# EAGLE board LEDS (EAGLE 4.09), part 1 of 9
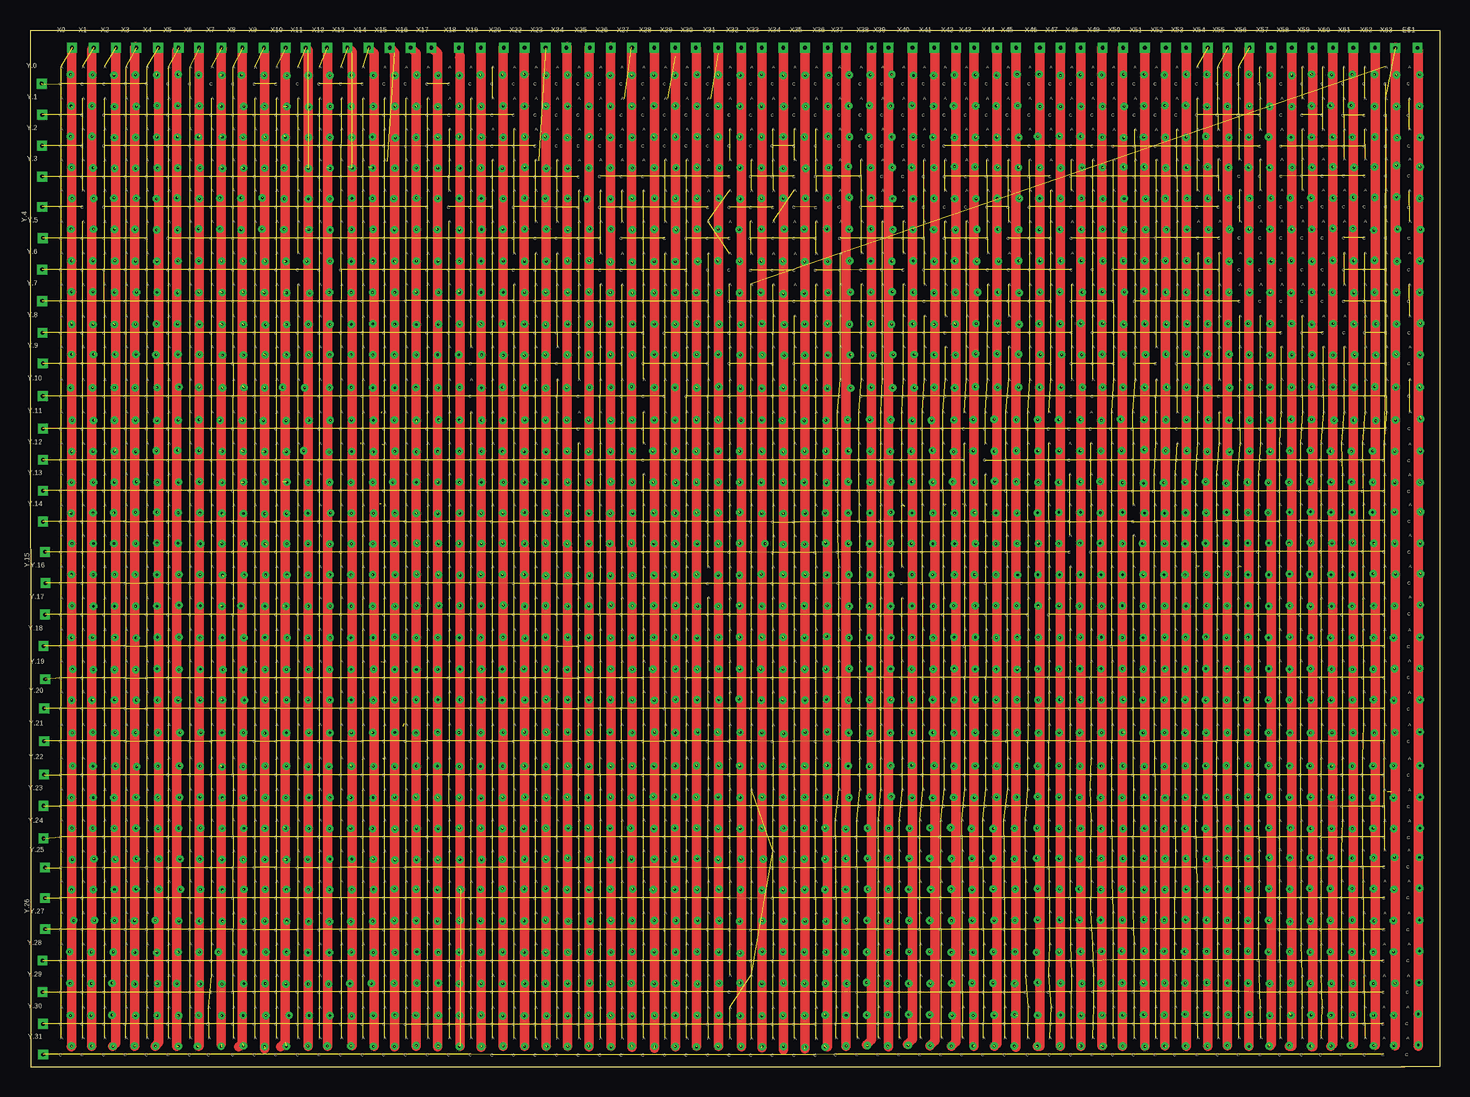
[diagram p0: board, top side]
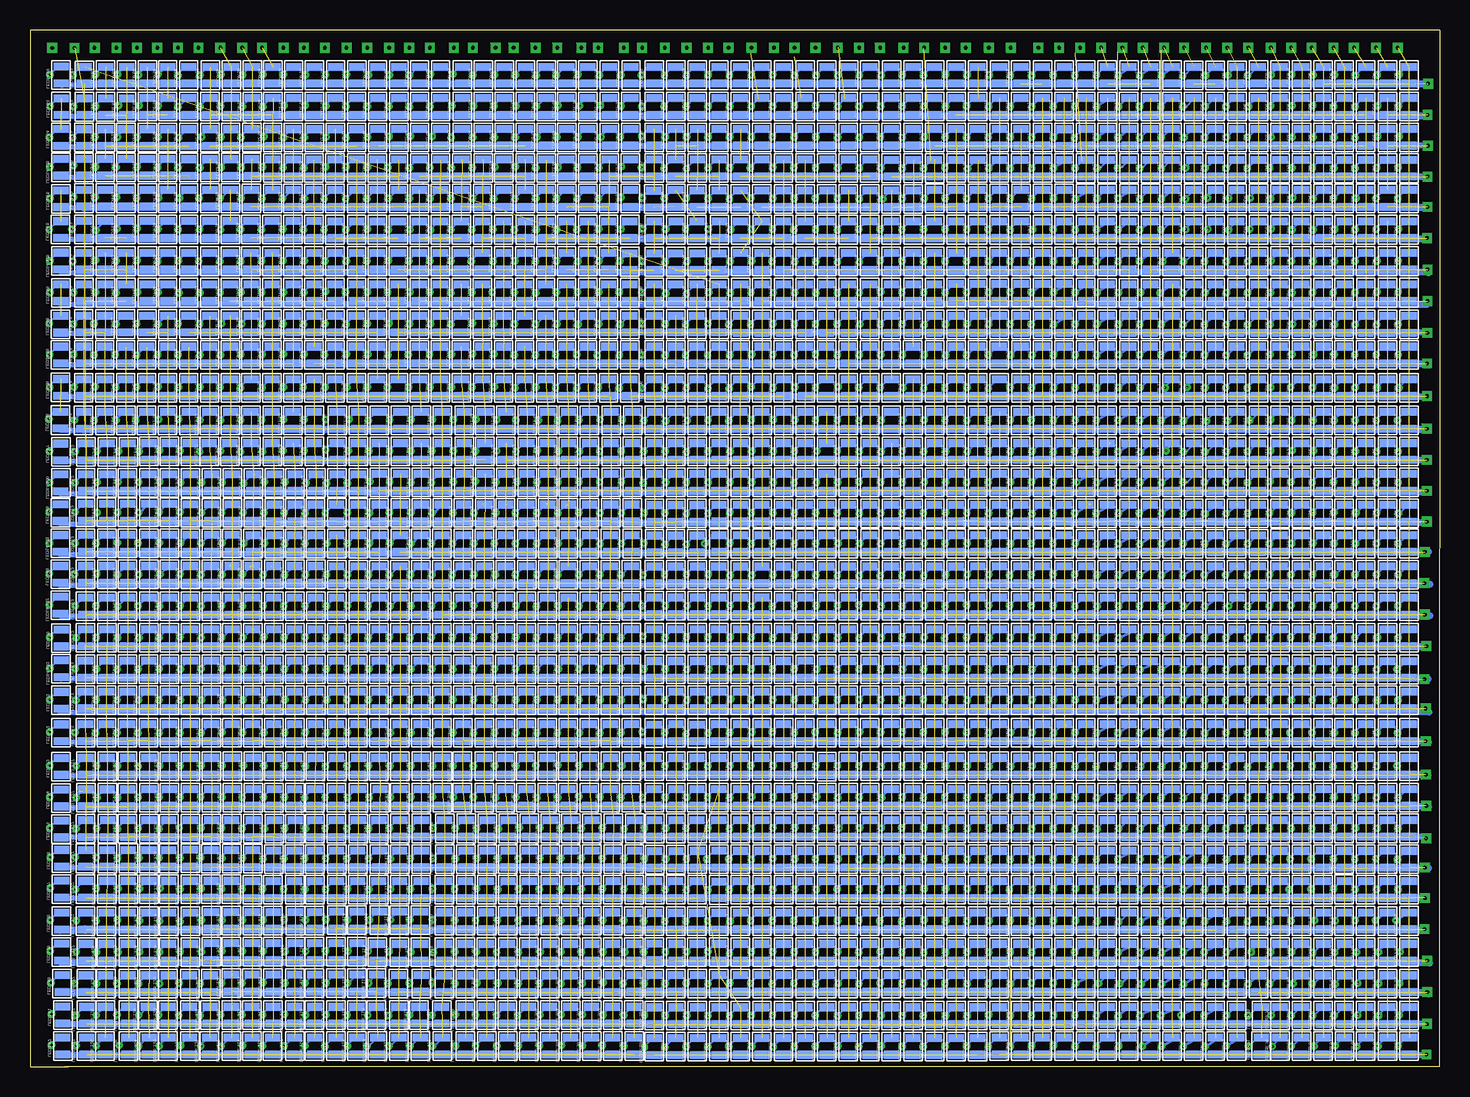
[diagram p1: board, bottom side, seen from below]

Size 117.52 x 86.45 mm. Coordinates in mm from the lower left corner, seen from the top.
Outline: 114.61,0 0.05,0 0,86.45 114.96,86.45
Outline: 114.96,86.45 114.99,86.45
Outline: 114.96,86.45 117.52,86.45 117.52,0 114.29,0
Copper layers used: Top, Bottom

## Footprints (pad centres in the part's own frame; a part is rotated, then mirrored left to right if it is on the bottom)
PAD0.012 = drill 0.305 pad 0.305 square: P$ 0,0
LED_603 = smd 1.27 x 0.635 bottom: P$A 0.004,-0.7; P$K 0.004,0.7

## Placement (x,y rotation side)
E$1  [PAD0.012]  115.68,84.96 0 top
LED0.0  LED_CROSS1/2  [LED_603]  2.57,82.68 180 top
LED0.1  LED_CROSS1/2  [LED_603]  4.37,82.68 180 top
LED0.2  LED_CROSS1/2  [LED_603]  6.18,82.68 180 top
LED0.3  LED_CROSS1/2  [LED_603]  7.97,82.68 180 top
LED0.4  LED_CROSS1/2  [LED_603]  9.72,82.68 180 top
LED0.5  LED_CROSS1/2  [LED_603]  11.52,82.68 180 top
LED0.6  LED_CROSS1/2  [LED_603]  13.32,82.68 180 top
LED0.7  LED_CROSS1/2  [LED_603]  15.12,82.68 180 top
LED0.8  LED_CROSS1/2  [LED_603]  16.92,82.67 180 top
LED0.9  LED_CROSS1/2  [LED_603]  18.72,82.67 180 top
LED0.10  LED_CROSS1/2  [LED_603]  20.52,82.67 180 top
LED0.11  LED_CROSS1/2  [LED_603]  22.32,82.68 180 top
LED0.12  LED_CROSS1/2  [LED_603]  24.12,82.68 180 top
LED0.13  LED_CROSS1/2  [LED_603]  25.91,82.68 180 top
LED0.14  LED_CROSS1/2  [LED_603]  27.72,82.68 180 top
LED0.15  LED_CROSS1/2  [LED_603]  29.52,82.68 180 top
LED0.16  LED_CROSS1/2  [LED_603]  31.3,82.68 180 top
LED0.17  LED_CROSS1/2  [LED_603]  33.12,82.68 180 top
LED0.18  LED_CROSS1/2  [LED_603]  34.92,82.68 180 top
LED0.19  LED_CROSS1/2  [LED_603]  36.7,82.68 180 top
LED0.20  LED_CROSS1/2  [LED_603]  38.52,82.68 180 top
LED0.21  LED_CROSS1/2  [LED_603]  40.32,82.68 180 top
LED0.22  LED_CROSS1/2  [LED_603]  42.12,82.68 180 top
LED0.23  LED_CROSS1/2  [LED_603]  43.9,82.68 180 top
LED0.24  LED_CROSS1/2  [LED_603]  45.7,82.68 180 top
LED0.25  LED_CROSS1/2  [LED_603]  47.51,82.68 180 top
LED0.26  LED_CROSS1/2  [LED_603]  49.28,82.68 180 top
LED0.27  LED_CROSS1/2  [LED_603]  51.1,82.68 180 top
LED0.28  LED_CROSS1/2  [LED_603]  52.91,82.68 180 top
LED0.29  LED_CROSS1/2  [LED_603]  54.71,82.68 180 top
LED0.30  LED_CROSS1/2  [LED_603]  56.51,82.68 180 top
LED0.31  LED_CROSS1/2  [LED_603]  58.3,82.68 180 top
LED0.32  LED_CROSS1/2  [LED_603]  60.09,82.68 180 top
LED0.33  LED_CROSS1/2  [LED_603]  61.91,82.68 180 top
LED0.34  LED_CROSS1/2  [LED_603]  63.7,82.68 180 top
LED0.35  LED_CROSS1/2  [LED_603]  65.49,82.68 180 top
LED0.37  LED_CROSS1/2  [LED_603]  67.42,82.68 180 top
LED0.38  LED_CROSS1/2  [LED_603]  69.22,82.68 180 top
LED0.39  LED_CROSS1/2  [LED_603]  71.02,82.68 180 top
LED0.40  LED_CROSS1/2  [LED_603]  72.77,82.68 180 top
LED0.41  LED_CROSS1/2  [LED_603]  74.5,82.68 180 top
LED0.42  LED_CROSS1/2  [LED_603]  76.22,82.68 180 top
LED0.43  LED_CROSS1/2  [LED_603]  78,82.68 180 top
LED0.44  LED_CROSS1/2  [LED_603]  79.75,82.68 180 top
LED0.45  LED_CROSS1/2  [LED_603]  81.47,82.68 180 top
LED0.46  LED_CROSS1/2  [LED_603]  83.3,82.68 180 top
LED0.47  LED_CROSS1/2  [LED_603]  85.05,82.68 180 top
LED0.48  LED_CROSS1/2  [LED_603]  86.77,82.68 180 top
LED0.49  LED_CROSS1/2  [LED_603]  88.55,82.68 180 top
LED0.50  LED_CROSS1/2  [LED_603]  90.27,82.68 180 top
LED0.51  LED_CROSS1/2  [LED_603]  92.05,82.68 180 top
LED0.52  LED_CROSS1/2  [LED_603]  93.82,82.68 180 top
LED0.53  LED_CROSS1/2  [LED_603]  95.55,82.68 180 top
LED0.54  LED_CROSS1/2  [LED_603]  97.27,82.68 180 top
LED0.55  LED_CROSS1/2  [LED_603]  99,82.68 180 top
LED0.56  LED_CROSS1/2  [LED_603]  100.75,82.68 180 top
LED0.57  LED_CROSS1/2  [LED_603]  102.5,82.68 180 top
LED0.58  LED_CROSS1/2  [LED_603]  104.3,82.68 180 top
LED0.59  LED_CROSS1/2  [LED_603]  106.05,82.68 180 top
LED0.60  LED_CROSS1/2  [LED_603]  107.75,82.68 180 top
LED0.61  LED_CROSS1/2  [LED_603]  109.47,82.68 180 top
LED0.62  LED_CROSS1/2  [LED_603]  111.22,82.68 180 top
LED1.0  LED_CROSS1/2  [LED_603]  2.57,80.08 180 top
LED1.1  LED_CROSS1/2  [LED_603]  4.37,80.08 180 top
LED1.2  LED_CROSS1/2  [LED_603]  6.18,80.08 180 top
LED1.3  LED_CROSS1/2  [LED_603]  7.97,80.08 180 top
LED1.4  LED_CROSS1/2  [LED_603]  9.72,80.08 180 top
LED1.5  LED_CROSS1/2  [LED_603]  11.52,80.08 180 top
LED1.6  LED_CROSS1/2  [LED_603]  13.32,80.08 180 top
LED1.7  LED_CROSS1/2  [LED_603]  15.12,80.08 180 top
LED1.8  LED_CROSS1/2  [LED_603]  16.92,80.08 180 top
LED1.9  LED_CROSS1/2  [LED_603]  18.72,80.08 180 top
LED1.10  LED_CROSS1/2  [LED_603]  20.52,80.08 180 top
LED1.11  LED_CROSS1/2  [LED_603]  22.32,80.08 180 top
LED1.12  LED_CROSS1/2  [LED_603]  24.12,80.08 180 top
LED1.13  LED_CROSS1/2  [LED_603]  25.92,80.08 180 top
LED1.14  LED_CROSS1/2  [LED_603]  27.72,80.08 180 top
LED1.15  LED_CROSS1/2  [LED_603]  29.52,80.08 180 top
LED1.16  LED_CROSS1/2  [LED_603]  31.33,80.08 180 top
LED1.17  LED_CROSS1/2  [LED_603]  33.12,80.08 180 top
LED1.18  LED_CROSS1/2  [LED_603]  34.92,80.08 180 top
LED1.19  LED_CROSS1/2  [LED_603]  36.72,80.08 180 top
LED1.20  LED_CROSS1/2  [LED_603]  38.52,80.08 180 top
LED1.21  LED_CROSS1/2  [LED_603]  40.32,80.08 180 top
LED1.22  LED_CROSS1/2  [LED_603]  42.12,80.08 180 top
LED1.23  LED_CROSS1/2  [LED_603]  43.9,80.08 180 top
LED1.24  LED_CROSS1/2  [LED_603]  45.7,80.08 180 top
LED1.25  LED_CROSS1/2  [LED_603]  47.51,80.08 180 top
LED1.26  LED_CROSS1/2  [LED_603]  49.31,80.08 180 top
LED1.27  LED_CROSS1/2  [LED_603]  51.1,80.08 180 top
LED1.28  LED_CROSS1/2  [LED_603]  52.91,80.08 180 top
LED1.29  LED_CROSS1/2  [LED_603]  54.71,80.08 180 top
LED1.30  LED_CROSS1/2  [LED_603]  56.51,80.08 180 top
LED1.31  LED_CROSS1/2  [LED_603]  58.3,80.08 180 top
LED1.32  LED_CROSS1/2  [LED_603]  60.09,80.08 180 top
LED1.33  LED_CROSS1/2  [LED_603]  61.91,80.08 180 top
LED1.34  LED_CROSS1/2  [LED_603]  63.7,80.08 180 top
LED1.35  LED_CROSS1/2  [LED_603]  65.49,80.08 180 top
LED1.36  LED_CROSS1/2  [LED_603]  114.97,56.65 180 top
LED1.37  LED_CROSS1/2  [LED_603]  67.44,80.08 180 top
LED1.38  LED_CROSS1/2  [LED_603]  69.22,80.08 180 top
LED1.39  LED_CROSS1/2  [LED_603]  71.02,80.08 180 top
LED1.40  LED_CROSS1/2  [LED_603]  72.77,80.08 180 top
LED1.41  LED_CROSS1/2  [LED_603]  74.5,80.08 180 top
LED1.42  LED_CROSS1/2  [LED_603]  76.22,80.08 180 top
LED1.43  LED_CROSS1/2  [LED_603]  78,80.08 180 top
LED1.44  LED_CROSS1/2  [LED_603]  79.75,80.08 180 top
LED1.45  LED_CROSS1/2  [LED_603]  81.47,80.08 180 top
LED1.46  LED_CROSS1/2  [LED_603]  83.3,80.08 180 top
LED1.47  LED_CROSS1/2  [LED_603]  85.05,80.08 180 top
LED1.48  LED_CROSS1/2  [LED_603]  86.77,80.08 180 top
LED1.49  LED_CROSS1/2  [LED_603]  88.55,80.08 180 top
LED1.50  LED_CROSS1/2  [LED_603]  90.3,80.08 180 top
LED1.51  LED_CROSS1/2  [LED_603]  92.07,80.08 180 top
LED1.52  LED_CROSS1/2  [LED_603]  93.82,80.08 180 top
LED1.53  LED_CROSS1/2  [LED_603]  95.55,80.08 180 top
LED1.54  LED_CROSS1/2  [LED_603]  97.27,80.08 180 top
LED1.55  LED_CROSS1/2  [LED_603]  99,80.08 180 top
LED1.56  LED_CROSS1/2  [LED_603]  100.75,80.08 180 top
LED1.57  LED_CROSS1/2  [LED_603]  102.52,80.08 180 top
LED1.58  LED_CROSS1/2  [LED_603]  104.3,80.08 180 top
LED1.59  LED_CROSS1/2  [LED_603]  106.05,80.08 180 top
LED1.60  LED_CROSS1/2  [LED_603]  107.75,80.08 180 top
LED1.61  LED_CROSS1/2  [LED_603]  109.47,80.06 180 top
LED1.62  LED_CROSS1/2  [LED_603]  111.22,80.06 180 top
LED1.63  LED_CROSS1/2  [LED_603]  113,80.06 180 top
LED1.64  LED_CROSS1/2  [LED_603]  114.92,80.06 180 top
LED1.65  LED_CROSS1/2  [LED_603]  114.94,72.39 180 top
LED1.66  LED_CROSS1/2  [LED_603]  114.94,64.55 180 top
LED2.0  LED_CROSS1/2  [LED_603]  2.57,77.51 180 top
LED2.1  LED_CROSS1/2  [LED_603]  4.37,77.51 180 top
LED2.2  LED_CROSS1/2  [LED_603]  6.18,77.51 180 top
LED2.3  LED_CROSS1/2  [LED_603]  7.97,77.51 180 top
LED2.4  LED_CROSS1/2  [LED_603]  9.72,77.51 180 top
LED2.5  LED_CROSS1/2  [LED_603]  11.52,77.51 180 top
LED2.6  LED_CROSS1/2  [LED_603]  13.33,77.51 180 top
LED2.7  LED_CROSS1/2  [LED_603]  15.12,77.51 180 top
LED2.8  LED_CROSS1/2  [LED_603]  16.92,77.51 180 top
LED2.9  LED_CROSS1/2  [LED_603]  18.73,77.5 180 top
LED2.10  LED_CROSS1/2  [LED_603]  20.52,77.5 180 top
LED2.11  LED_CROSS1/2  [LED_603]  22.32,77.5 180 top
LED2.12  LED_CROSS1/2  [LED_603]  24.12,77.51 180 top
LED2.13  LED_CROSS1/2  [LED_603]  25.92,77.51 180 top
LED2.14  LED_CROSS1/2  [LED_603]  27.72,77.5 180 top
LED2.15  LED_CROSS1/2  [LED_603]  29.51,77.51 180 top
LED2.16  LED_CROSS1/2  [LED_603]  31.33,77.48 180 top
LED2.17  LED_CROSS1/2  [LED_603]  33.12,77.51 180 top
LED2.18  LED_CROSS1/2  [LED_603]  34.92,77.51 180 top
LED2.19  LED_CROSS1/2  [LED_603]  36.73,77.51 180 top
LED2.20  LED_CROSS1/2  [LED_603]  38.52,77.51 180 top
LED2.21  LED_CROSS1/2  [LED_603]  40.32,77.51 180 top
LED2.22  LED_CROSS1/2  [LED_603]  42.12,77.51 180 top
LED2.23  LED_CROSS1/2  [LED_603]  43.9,77.51 180 top
LED2.24  LED_CROSS1/2  [LED_603]  45.73,77.51 180 top
LED2.25  LED_CROSS1/2  [LED_603]  47.51,77.51 180 top
LED2.26  LED_CROSS1/2  [LED_603]  49.31,77.51 180 top
LED2.27  LED_CROSS1/2  [LED_603]  51.1,77.51 180 top
LED2.28  LED_CROSS1/2  [LED_603]  52.92,77.51 180 top
LED2.29  LED_CROSS1/2  [LED_603]  54.71,77.51 180 top
LED2.30  LED_CROSS1/2  [LED_603]  56.51,77.51 180 top
LED2.31  LED_CROSS1/2  [LED_603]  58.3,77.51 180 top
LED2.32  LED_CROSS1/2  [LED_603]  60.09,77.51 180 top
LED2.33  LED_CROSS1/2  [LED_603]  61.89,77.51 180 top
LED2.34  LED_CROSS1/2  [LED_603]  63.7,77.51 180 top
LED2.35  LED_CROSS1/2  [LED_603]  65.5,77.51 180 top
LED2.36  LED_CROSS1/2  [LED_603]  114.99,53.93 180 top
LED2.37  LED_CROSS1/2  [LED_603]  67.44,77.51 180 top
LED2.38  LED_CROSS1/2  [LED_603]  69.22,77.51 180 top
LED2.39  LED_CROSS1/2  [LED_603]  71.02,77.51 180 top
LED2.40  LED_CROSS1/2  [LED_603]  72.77,77.51 180 top
LED2.41  LED_CROSS1/2  [LED_603]  74.5,77.51 180 top
LED2.42  LED_CROSS1/2  [LED_603]  76.22,77.51 180 top
LED2.43  LED_CROSS1/2  [LED_603]  78,77.51 180 top
LED2.44  LED_CROSS1/2  [LED_603]  79.75,77.51 180 top
LED2.45  LED_CROSS1/2  [LED_603]  81.5,77.51 180 top
LED2.46  LED_CROSS1/2  [LED_603]  83.3,77.51 180 top
LED2.47  LED_CROSS1/2  [LED_603]  85.05,77.51 180 top
LED2.48  LED_CROSS1/2  [LED_603]  86.77,77.51 180 top
LED2.49  LED_CROSS1/2  [LED_603]  88.55,77.51 180 top
LED2.50  LED_CROSS1/2  [LED_603]  90.3,77.48 180 top
LED2.51  LED_CROSS1/2  [LED_603]  92.07,77.48 180 top
LED2.52  LED_CROSS1/2  [LED_603]  93.82,77.48 180 top
LED2.53  LED_CROSS1/2  [LED_603]  95.57,77.48 180 top
LED2.54  LED_CROSS1/2  [LED_603]  97.3,77.48 180 top
LED2.55  LED_CROSS1/2  [LED_603]  99.02,77.48 180 top
LED2.56  LED_CROSS1/2  [LED_603]  100.8,77.48 180 top
LED2.57  LED_CROSS1/2  [LED_603]  102.52,77.48 180 top
LED2.58  LED_CROSS1/2  [LED_603]  104.3,77.48 180 top
LED2.59  LED_CROSS1/2  [LED_603]  106.05,77.48 180 top
LED2.60  LED_CROSS1/2  [LED_603]  107.75,77.48 180 top
LED2.61  LED_CROSS1/2  [LED_603]  109.52,77.48 180 top
LED2.62  LED_CROSS1/2  [LED_603]  111.25,77.48 180 top
LED2.63  LED_CROSS1/2  [LED_603]  113.02,77.48 180 top
LED2.64  LED_CROSS1/2  [LED_603]  114.95,77.5 180 top
LED2.65  LED_CROSS1/2  [LED_603]  114.97,69.81 180 top
LED2.66  LED_CROSS1/2  [LED_603]  114.97,61.92 180 top
LED2.67  LED_CROSS1/2  [LED_603]  114.96,51.27 180 top
LED2.68  LED_CROSS1/2  [LED_603]  114.98,46.21 180 top
LED2.69  LED_CROSS1/2  [LED_603]  114.98,41.06 180 top
LED2.70  LED_CROSS1/2  [LED_603]  114.93,35.76 180 top
LED2.71  LED_CROSS1/2  [LED_603]  114.93,30.56 180 top
LED2.72  LED_CROSS1/2  [LED_603]  114.93,27.86 180 top
LED2.73  LED_CROSS1/2  [LED_603]  114.93,25.05 180 top
LED2.74  LED_CROSS1/2  [LED_603]  114.93,22.42 180 top
LED2.75  LED_CROSS1/2  [LED_603]  114.93,19.84 180 top
LED2.76  LED_CROSS1/2  [LED_603]  114.89,17.4 180 top
LED2.77  LED_CROSS1/2  [LED_603]  114.89,14.83 180 top
LED2.78  LED_CROSS1/2  [LED_603]  114.89,12.16 180 top
LED2.79  LED_CROSS1/2  [LED_603]  114.89,9.58 180 top
LED2.80  LED_CROSS1/2  [LED_603]  114.84,6.95 180 top
LED2.81  LED_CROSS1/2  [LED_603]  114.79,4.33 180 top
LED2.82  LED_CROSS1/2  [LED_603]  114.79,1.75 180 top
LED3.0  LED_CROSS1/2  [LED_603]  2.57,74.93 180 top
LED3.1  LED_CROSS1/2  [LED_603]  4.37,74.93 180 top
LED3.2  LED_CROSS1/2  [LED_603]  6.18,74.93 180 top
LED3.3  LED_CROSS1/2  [LED_603]  7.97,74.93 180 top
LED3.4  LED_CROSS1/2  [LED_603]  9.72,74.93 180 top
LED3.5  LED_CROSS1/2  [LED_603]  11.52,74.93 180 top
LED3.6  LED_CROSS1/2  [LED_603]  13.33,74.93 180 top
LED3.7  LED_CROSS1/2  [LED_603]  15.12,74.93 180 top
LED3.8  LED_CROSS1/2  [LED_603]  16.92,74.93 180 top
LED3.9  LED_CROSS1/2  [LED_603]  18.72,74.93 180 top
LED3.10  LED_CROSS1/2  [LED_603]  20.52,74.93 180 top
LED3.11  LED_CROSS1/2  [LED_603]  22.32,74.93 180 top
LED3.12  LED_CROSS1/2  [LED_603]  24.12,74.93 180 top
LED3.13  LED_CROSS1/2  [LED_603]  25.92,74.93 180 top
LED3.14  LED_CROSS1/2  [LED_603]  27.72,74.93 180 top
LED3.15  LED_CROSS1/2  [LED_603]  29.51,74.93 180 top
LED3.16  LED_CROSS1/2  [LED_603]  31.33,74.94 180 top
LED3.17  LED_CROSS1/2  [LED_603]  33.12,74.94 180 top
LED3.18  LED_CROSS1/2  [LED_603]  34.94,74.94 180 top
LED3.19  LED_CROSS1/2  [LED_603]  36.71,74.94 180 top
LED3.20  LED_CROSS1/2  [LED_603]  38.52,74.94 180 top
LED3.21  LED_CROSS1/2  [LED_603]  40.31,74.94 180 top
LED3.22  LED_CROSS1/2  [LED_603]  42.12,74.93 180 top
LED3.23  LED_CROSS1/2  [LED_603]  43.9,74.93 180 top
LED3.24  LED_CROSS1/2  [LED_603]  45.73,74.93 180 top
LED3.25  LED_CROSS1/2  [LED_603]  47.51,74.96 180 top
LED3.26  LED_CROSS1/2  [LED_603]  49.31,74.96 180 top
LED3.27  LED_CROSS1/2  [LED_603]  51.1,74.96 180 top
LED3.28  LED_CROSS1/2  [LED_603]  52.92,74.96 180 top
LED3.29  LED_CROSS1/2  [LED_603]  54.71,74.96 180 top
LED3.30  LED_CROSS1/2  [LED_603]  56.51,74.96 180 top
LED3.31  LED_CROSS1/2  [LED_603]  58.3,74.96 180 top
LED3.32  LED_CROSS1/2  [LED_603]  60.09,74.96 180 top
LED3.33  LED_CROSS1/2  [LED_603]  61.89,74.96 180 top
LED3.34  LED_CROSS1/2  [LED_603]  63.7,74.96 180 top
LED3.35  LED_CROSS1/2  [LED_603]  65.5,74.96 180 top
LED3.37  LED_CROSS1/2  [LED_603]  67.47,74.96 180 top
LED3.38  LED_CROSS1/2  [LED_603]  69.25,74.96 180 top
LED3.39  LED_CROSS1/2  [LED_603]  71.02,74.96 180 top
LED3.40  LED_CROSS1/2  [LED_603]  72.77,74.96 180 top
LED3.41  LED_CROSS1/2  [LED_603]  74.5,74.96 180 top
LED3.42  LED_CROSS1/2  [LED_603]  76.25,74.96 180 top
LED3.43  LED_CROSS1/2  [LED_603]  78.02,74.96 180 top
LED3.44  LED_CROSS1/2  [LED_603]  79.75,74.96 180 top
LED3.45  LED_CROSS1/2  [LED_603]  81.52,74.96 180 top
LED3.46  LED_CROSS1/2  [LED_603]  83.3,74.96 180 top
LED3.47  LED_CROSS1/2  [LED_603]  85.05,74.96 180 top
LED3.48  LED_CROSS1/2  [LED_603]  86.8,74.96 180 top
LED3.49  LED_CROSS1/2  [LED_603]  88.57,74.96 180 top
LED3.50  LED_CROSS1/2  [LED_603]  90.3,74.96 180 top
LED3.51  LED_CROSS1/2  [LED_603]  92.09,74.96 180 top
LED3.52  LED_CROSS1/2  [LED_603]  93.87,74.96 180 top
LED3.53  LED_CROSS1/2  [LED_603]  95.57,74.96 180 top
LED3.54  LED_CROSS1/2  [LED_603]  97.3,74.96 180 top
LED3.55  LED_CROSS1/2  [LED_603]  99.05,74.98 180 top
LED3.56  LED_CROSS1/2  [LED_603]  100.8,74.98 180 top
LED3.57  LED_CROSS1/2  [LED_603]  102.52,74.98 180 top
LED3.58  LED_CROSS1/2  [LED_603]  104.3,74.98 180 top
LED3.59  LED_CROSS1/2  [LED_603]  106.05,75.01 180 top
LED3.60  LED_CROSS1/2  [LED_603]  107.75,75.01 180 top
LED3.61  LED_CROSS1/2  [LED_603]  109.52,75.01 180 top
LED3.62  LED_CROSS1/2  [LED_603]  111.27,75.01 180 top
LED3.63  LED_CROSS1/2  [LED_603]  113.02,75.01 180 top
LED4.0  LED_CROSS1/2  [LED_603]  2.57,72.41 180 top
LED4.1  LED_CROSS1/2  [LED_603]  4.37,72.41 180 top
LED4.2  LED_CROSS1/2  [LED_603]  6.18,72.41 180 top
LED4.3  LED_CROSS1/2  [LED_603]  7.97,72.41 180 top
LED4.4  LED_CROSS1/2  [LED_603]  9.72,72.41 180 top
LED4.5  LED_CROSS1/2  [LED_603]  11.52,72.41 180 top
LED4.6  LED_CROSS1/2  [LED_603]  13.33,72.41 180 top
LED4.7  LED_CROSS1/2  [LED_603]  15.12,72.41 180 top
LED4.8  LED_CROSS1/2  [LED_603]  16.92,72.41 180 top
LED4.9  LED_CROSS1/2  [LED_603]  18.72,72.41 180 top
LED4.10  LED_CROSS1/2  [LED_603]  20.52,72.41 180 top
LED4.11  LED_CROSS1/2  [LED_603]  22.32,72.41 180 top
LED4.12  LED_CROSS1/2  [LED_603]  24.12,72.41 180 top
LED4.13  LED_CROSS1/2  [LED_603]  25.92,72.41 180 top
LED4.14  LED_CROSS1/2  [LED_603]  27.72,72.41 180 top
LED4.15  LED_CROSS1/2  [LED_603]  29.52,72.41 180 top
LED4.16  LED_CROSS1/2  [LED_603]  31.32,72.4 180 top
LED4.17  LED_CROSS1/2  [LED_603]  33.12,72.4 180 top
LED4.18  LED_CROSS1/2  [LED_603]  34.91,72.4 180 top
LED4.19  LED_CROSS1/2  [LED_603]  36.71,72.4 180 top
LED4.20  LED_CROSS1/2  [LED_603]  38.52,72.4 180 top
LED4.21  LED_CROSS1/2  [LED_603]  40.31,72.4 180 top
LED4.22  LED_CROSS1/2  [LED_603]  42.12,72.41 180 top
LED4.23  LED_CROSS1/2  [LED_603]  43.9,72.38 180 top
LED4.24  LED_CROSS1/2  [LED_603]  45.73,72.38 180 top
LED4.25  LED_CROSS1/2  [LED_603]  47.51,72.38 180 top
LED4.26  LED_CROSS1/2  [LED_603]  49.31,72.38 180 top
LED4.27  LED_CROSS1/2  [LED_603]  51.1,72.38 180 top
LED4.28  LED_CROSS1/2  [LED_603]  52.92,72.38 180 top
LED4.29  LED_CROSS1/2  [LED_603]  54.71,72.38 180 top
LED4.30  LED_CROSS1/2  [LED_603]  56.51,72.38 180 top
LED4.31  LED_CROSS1/2  [LED_603]  58.3,72.38 180 top
LED4.32  LED_CROSS1/2  [LED_603]  60.1,72.38 180 top
LED4.33  LED_CROSS1/2  [LED_603]  61.93,72.38 180 top
LED4.34  LED_CROSS1/2  [LED_603]  63.7,72.41 180 top
LED4.35  LED_CROSS1/2  [LED_603]  65.52,72.36 180 top
LED4.37  LED_CROSS1/2  [LED_603]  67.47,72.41 180 top
LED4.38  LED_CROSS1/2  [LED_603]  69.27,72.41 180 top
LED4.39  LED_CROSS1/2  [LED_603]  71.02,72.41 180 top
LED4.40  LED_CROSS1/2  [LED_603]  72.77,72.41 180 top
LED4.41  LED_CROSS1/2  [LED_603]  74.5,72.41 180 top
LED4.42  LED_CROSS1/2  [LED_603]  76.25,72.41 180 top
LED4.43  LED_CROSS1/2  [LED_603]  78.02,72.41 180 top
LED4.44  LED_CROSS1/2  [LED_603]  79.8,72.41 180 top
LED4.45  LED_CROSS1/2  [LED_603]  81.55,72.41 180 top
LED4.46  LED_CROSS1/2  [LED_603]  83.32,72.41 180 top
LED4.47  LED_CROSS1/2  [LED_603]  85.07,72.41 180 top
LED4.48  LED_CROSS1/2  [LED_603]  86.8,72.41 180 top
LED4.49  LED_CROSS1/2  [LED_603]  88.57,72.41 180 top
LED4.50  LED_CROSS1/2  [LED_603]  90.3,72.41 180 top
LED4.51  LED_CROSS1/2  [LED_603]  92.09,72.41 180 top
LED4.52  LED_CROSS1/2  [LED_603]  93.87,72.41 180 top
LED4.53  LED_CROSS1/2  [LED_603]  95.59,72.41 180 top
LED4.54  LED_CROSS1/2  [LED_603]  97.3,72.41 180 top
LED4.55  LED_CROSS1/2  [LED_603]  99.07,72.41 180 top
LED4.56  LED_CROSS1/2  [LED_603]  100.82,72.43 180 top
LED4.57  LED_CROSS1/2  [LED_603]  102.52,72.43 180 top
LED4.58  LED_CROSS1/2  [LED_603]  104.3,72.43 180 top
LED4.59  LED_CROSS1/2  [LED_603]  106.05,72.43 180 top
LED4.60  LED_CROSS1/2  [LED_603]  107.75,72.43 180 top
LED4.61  LED_CROSS1/2  [LED_603]  109.52,72.43 180 top
LED4.62  LED_CROSS1/2  [LED_603]  111.25,72.43 180 top
LED4.63  LED_CROSS1/2  [LED_603]  113.02,72.43 180 top
LED5.0  LED_CROSS1/2  [LED_603]  2.57,69.81 180 top
LED5.1  LED_CROSS1/2  [LED_603]  4.37,69.81 180 top
LED5.2  LED_CROSS1/2  [LED_603]  6.18,69.81 180 top
LED5.3  LED_CROSS1/2  [LED_603]  7.97,69.81 180 top
LED5.4  LED_CROSS1/2  [LED_603]  9.72,69.81 180 top
LED5.5  LED_CROSS1/2  [LED_603]  11.52,69.81 180 top
LED5.6  LED_CROSS1/2  [LED_603]  13.32,69.81 180 top
LED5.7  LED_CROSS1/2  [LED_603]  15.12,69.81 180 top
LED5.8  LED_CROSS1/2  [LED_603]  16.92,69.81 180 top
LED5.9  LED_CROSS1/2  [LED_603]  18.72,69.81 180 top
LED5.10  LED_CROSS1/2  [LED_603]  20.52,69.81 180 top
LED5.11  LED_CROSS1/2  [LED_603]  22.32,69.81 180 top
LED5.12  LED_CROSS1/2  [LED_603]  24.12,69.81 180 top
LED5.13  LED_CROSS1/2  [LED_603]  25.91,69.81 180 top
LED5.14  LED_CROSS1/2  [LED_603]  27.72,69.81 180 top
LED5.15  LED_CROSS1/2  [LED_603]  29.51,69.81 180 top
LED5.16  LED_CROSS1/2  [LED_603]  31.32,69.81 180 top
LED5.17  LED_CROSS1/2  [LED_603]  33.12,69.81 180 top
LED5.18  LED_CROSS1/2  [LED_603]  34.91,69.81 180 top
LED5.19  LED_CROSS1/2  [LED_603]  36.73,69.81 180 top
LED5.20  LED_CROSS1/2  [LED_603]  38.52,69.81 180 top
LED5.21  LED_CROSS1/2  [LED_603]  40.31,69.81 180 top
LED5.22  LED_CROSS1/2  [LED_603]  42.12,69.81 180 top
LED5.23  LED_CROSS1/2  [LED_603]  43.9,69.81 180 top
LED5.24  LED_CROSS1/2  [LED_603]  45.73,69.81 180 top
LED5.25  LED_CROSS1/2  [LED_603]  47.53,69.81 180 top
LED5.26  LED_CROSS1/2  [LED_603]  49.3,69.81 180 top
LED5.27  LED_CROSS1/2  [LED_603]  51.1,69.81 180 top
LED5.28  LED_CROSS1/2  [LED_603]  52.91,69.81 180 top
LED5.29  LED_CROSS1/2  [LED_603]  54.71,69.81 180 top
LED5.31  LED_CROSS1/2  [LED_603]  56.49,69.81 180 top
LED5.32  LED_CROSS1/2  [LED_603]  58.3,69.81 180 top
LED5.33  LED_CROSS1/2  [LED_603]  60.05,69.81 180 top
LED5.34  LED_CROSS1/2  [LED_603]  61.93,69.81 180 top
LED5.35  LED_CROSS1/2  [LED_603]  63.68,69.81 180 top
LED5.36  LED_CROSS1/2  [LED_603]  65.49,69.81 180 top
LED5.37  LED_CROSS1/2  [LED_603]  67.52,69.81 180 top
LED5.38  LED_CROSS1/2  [LED_603]  69.3,69.81 180 top
LED5.39  LED_CROSS1/2  [LED_603]  71.02,69.81 180 top
LED5.40  LED_CROSS1/2  [LED_603]  72.8,69.81 180 top
LED5.41  LED_CROSS1/2  [LED_603]  74.5,69.81 180 top
LED5.42  LED_CROSS1/2  [LED_603]  76.25,69.81 180 top
LED5.43  LED_CROSS1/2  [LED_603]  78.05,69.81 180 top
LED5.44  LED_CROSS1/2  [LED_603]  79.8,69.81 180 top
LED5.45  LED_CROSS1/2  [LED_603]  81.57,69.81 180 top
LED5.46  LED_CROSS1/2  [LED_603]  83.32,69.81 180 top
LED5.47  LED_CROSS1/2  [LED_603]  85.07,69.81 180 top
LED5.48  LED_CROSS1/2  [LED_603]  86.82,69.81 180 top
LED5.49  LED_CROSS1/2  [LED_603]  88.57,69.81 180 top
LED5.50  LED_CROSS1/2  [LED_603]  90.3,69.81 180 top
LED5.51  LED_CROSS1/2  [LED_603]  92.09,69.81 180 top
LED5.52  LED_CROSS1/2  [LED_603]  93.84,69.83 180 top
LED5.53  LED_CROSS1/2  [LED_603]  95.59,69.83 180 top
LED5.54  LED_CROSS1/2  [LED_603]  97.34,69.83 180 top
LED5.55  LED_CROSS1/2  [LED_603]  99.12,69.83 180 top
LED5.56  LED_CROSS1/2  [LED_603]  100.82,69.83 180 top
LED5.57  LED_CROSS1/2  [LED_603]  102.55,69.83 180 top
LED5.58  LED_CROSS1/2  [LED_603]  104.3,69.83 180 top
LED5.59  LED_CROSS1/2  [LED_603]  106.05,69.83 180 top
LED5.60  LED_CROSS1/2  [LED_603]  107.75,69.83 180 top
LED5.61  LED_CROSS1/2  [LED_603]  109.52,69.83 180 top
LED5.62  LED_CROSS1/2  [LED_603]  111.25,69.83 180 top
LED5.63  LED_CROSS1/2  [LED_603]  113.02,69.83 180 top
LED6.0  LED_CROSS1/2  [LED_603]  2.57,67.18 180 top
LED6.1  LED_CROSS1/2  [LED_603]  4.37,67.18 180 top
LED6.2  LED_CROSS1/2  [LED_603]  6.18,67.18 180 top
LED6.3  LED_CROSS1/2  [LED_603]  7.97,67.18 180 top
LED6.4  LED_CROSS1/2  [LED_603]  9.73,67.18 180 top
LED6.5  LED_CROSS1/2  [LED_603]  11.52,67.18 180 top
LED6.6  LED_CROSS1/2  [LED_603]  13.32,67.18 180 top
LED6.7  LED_CROSS1/2  [LED_603]  15.12,67.17 180 top
LED6.8  LED_CROSS1/2  [LED_603]  16.92,67.17 180 top
LED6.9  LED_CROSS1/2  [LED_603]  18.72,67.17 180 top
LED6.10  LED_CROSS1/2  [LED_603]  20.52,67.17 180 top
LED6.11  LED_CROSS1/2  [LED_603]  22.32,67.17 180 top
LED6.12  LED_CROSS1/2  [LED_603]  24.12,67.17 180 top
LED6.13  LED_CROSS1/2  [LED_603]  25.92,67.17 180 top
LED6.14  LED_CROSS1/2  [LED_603]  27.72,67.17 180 top
LED6.15  LED_CROSS1/2  [LED_603]  29.51,67.17 180 top
LED6.16  LED_CROSS1/2  [LED_603]  31.32,67.16 180 top
LED6.17  LED_CROSS1/2  [LED_603]  33.12,67.16 180 top
LED6.18  LED_CROSS1/2  [LED_603]  34.91,67.16 180 top
LED6.19  LED_CROSS1/2  [LED_603]  36.73,67.16 180 top
LED6.20  LED_CROSS1/2  [LED_603]  38.52,67.16 180 top
LED6.21  LED_CROSS1/2  [LED_603]  40.31,67.16 180 top
LED6.22  LED_CROSS1/2  [LED_603]  42.12,67.16 180 top
LED6.23  LED_CROSS1/2  [LED_603]  43.9,67.16 180 top
LED6.24  LED_CROSS1/2  [LED_603]  45.73,67.16 180 top
LED6.25  LED_CROSS1/2  [LED_603]  47.53,67.16 180 top
LED6.26  LED_CROSS1/2  [LED_603]  49.3,67.16 180 top
LED6.27  LED_CROSS1/2  [LED_603]  51.1,67.16 180 top
LED6.28  LED_CROSS1/2  [LED_603]  52.91,67.16 180 top
LED6.29  LED_CROSS1/2  [LED_603]  54.71,67.16 180 top
LED6.30  LED_CROSS1/2  [LED_603]  56.51,67.16 180 top
LED6.31  LED_CROSS1/2  [LED_603]  58.29,67.16 180 top
LED6.33  LED_CROSS1/2  [LED_603]  60.09,67.14 180 top
LED6.34  LED_CROSS1/2  [LED_603]  61.91,67.14 180 top
LED6.35  LED_CROSS1/2  [LED_603]  63.7,67.14 180 top
LED6.36  LED_CROSS1/2  [LED_603]  65.49,67.14 180 top
LED6.37  LED_CROSS1/2  [LED_603]  67.52,67.14 180 top
LED6.38  LED_CROSS1/2  [LED_603]  69.3,67.18 180 top
LED6.39  LED_CROSS1/2  [LED_603]  71.02,67.18 180 top
LED6.40  LED_CROSS1/2  [LED_603]  72.8,67.18 180 top
LED6.41  LED_CROSS1/2  [LED_603]  74.52,67.18 180 top
LED6.42  LED_CROSS1/2  [LED_603]  76.27,67.18 180 top
LED6.43  LED_CROSS1/2  [LED_603]  78.05,67.18 180 top
LED6.44  LED_CROSS1/2  [LED_603]  79.82,67.18 180 top
LED6.45  LED_CROSS1/2  [LED_603]  81.57,67.18 180 top
LED6.46  LED_CROSS1/2  [LED_603]  83.32,67.18 180 top
LED6.47  LED_CROSS1/2  [LED_603]  85.07,67.18 180 top
LED6.48  LED_CROSS1/2  [LED_603]  86.82,67.18 180 top
LED6.49  LED_CROSS1/2  [LED_603]  88.57,67.18 180 top
LED6.50  LED_CROSS1/2  [LED_603]  90.3,67.18 180 top
LED6.51  LED_CROSS1/2  [LED_603]  92.09,67.18 180 top
LED6.52  LED_CROSS1/2  [LED_603]  93.84,67.18 180 top
LED6.53  LED_CROSS1/2  [LED_603]  95.59,67.18 180 top
LED6.54  LED_CROSS1/2  [LED_603]  97.34,67.18 180 top
LED6.55  LED_CROSS1/2  [LED_603]  99.12,67.18 180 top
LED6.56  LED_CROSS1/2  [LED_603]  100.82,67.18 180 top
LED6.57  LED_CROSS1/2  [LED_603]  102.55,67.18 180 top
LED6.58  LED_CROSS1/2  [LED_603]  104.3,67.18 180 top
LED6.59  LED_CROSS1/2  [LED_603]  106.05,67.18 180 top
LED6.60  LED_CROSS1/2  [LED_603]  107.75,67.18 180 top
LED6.61  LED_CROSS1/2  [LED_603]  109.52,67.18 180 top
LED6.62  LED_CROSS1/2  [LED_603]  111.25,67.18 180 top
LED6.63  LED_CROSS1/2  [LED_603]  113.02,67.18 180 top
LED7.0  LED_CROSS1/2  [LED_603]  2.57,64.56 180 top
LED7.1  LED_CROSS1/2  [LED_603]  4.37,64.56 180 top
LED7.2  LED_CROSS1/2  [LED_603]  6.17,64.56 180 top
LED7.3  LED_CROSS1/2  [LED_603]  7.97,64.56 180 top
LED7.4  LED_CROSS1/2  [LED_603]  9.73,64.56 180 top
LED7.5  LED_CROSS1/2  [LED_603]  11.52,64.56 180 top
LED7.6  LED_CROSS1/2  [LED_603]  13.32,64.56 180 top
LED7.7  LED_CROSS1/2  [LED_603]  15.12,64.56 180 top
LED7.8  LED_CROSS1/2  [LED_603]  16.92,64.56 180 top
LED7.9  LED_CROSS1/2  [LED_603]  18.72,64.56 180 top
LED7.10  LED_CROSS1/2  [LED_603]  20.52,64.56 180 top
LED7.11  LED_CROSS1/2  [LED_603]  22.32,64.55 180 top
LED7.12  LED_CROSS1/2  [LED_603]  24.12,64.55 180 top
LED7.13  LED_CROSS1/2  [LED_603]  25.93,64.55 180 top
LED7.14  LED_CROSS1/2  [LED_603]  27.72,64.55 180 top
LED7.15  LED_CROSS1/2  [LED_603]  29.51,64.57 180 top
LED7.16  LED_CROSS1/2  [LED_603]  31.32,64.58 180 top
LED7.17  LED_CROSS1/2  [LED_603]  33.12,64.58 180 top
LED7.18  LED_CROSS1/2  [LED_603]  34.91,64.58 180 top
LED7.19  LED_CROSS1/2  [LED_603]  36.73,64.58 180 top
LED7.20  LED_CROSS1/2  [LED_603]  38.52,64.58 180 top
LED7.21  LED_CROSS1/2  [LED_603]  40.31,64.58 180 top
LED7.22  LED_CROSS1/2  [LED_603]  42.12,64.56 180 top
LED7.23  LED_CROSS1/2  [LED_603]  43.9,64.56 180 top
LED7.24  LED_CROSS1/2  [LED_603]  45.73,64.56 180 top
LED7.25  LED_CROSS1/2  [LED_603]  47.53,64.56 180 top
LED7.26  LED_CROSS1/2  [LED_603]  49.3,64.56 180 top
LED7.27  LED_CROSS1/2  [LED_603]  51.1,64.56 180 top
LED7.28  LED_CROSS1/2  [LED_603]  52.91,64.56 180 top
LED7.29  LED_CROSS1/2  [LED_603]  54.71,64.56 180 top
LED7.30  LED_CROSS1/2  [LED_603]  56.51,64.56 180 top
LED7.31  LED_CROSS1/2  [LED_603]  58.29,64.56 180 top
LED7.33  LED_CROSS1/2  [LED_603]  60.09,64.56 180 top
LED7.34  LED_CROSS1/2  [LED_603]  61.91,64.56 180 top
LED7.35  LED_CROSS1/2  [LED_603]  63.7,64.56 180 top
LED7.36  LED_CROSS1/2  [LED_603]  65.49,64.56 180 top
LED7.37  LED_CROSS1/2  [LED_603]  67.52,64.56 180 top
LED7.38  LED_CROSS1/2  [LED_603]  69.3,64.56 180 top
LED7.39  LED_CROSS1/2  [LED_603]  71.02,64.56 180 top
LED7.40  LED_CROSS1/2  [LED_603]  72.8,64.56 180 top
LED7.41  LED_CROSS1/2  [LED_603]  74.55,64.56 180 top
LED7.42  LED_CROSS1/2  [LED_603]  76.3,64.56 180 top
LED7.43  LED_CROSS1/2  [LED_603]  78.05,64.56 180 top
LED7.44  LED_CROSS1/2  [LED_603]  79.82,64.56 180 top
LED7.45  LED_CROSS1/2  [LED_603]  81.57,64.56 180 top
LED7.46  LED_CROSS1/2  [LED_603]  83.32,64.56 180 top
LED7.47  LED_CROSS1/2  [LED_603]  85.07,64.56 180 top
LED7.48  LED_CROSS1/2  [LED_603]  86.82,64.56 180 top
LED7.49  LED_CROSS1/2  [LED_603]  88.57,64.56 180 top
LED7.50  LED_CROSS1/2  [LED_603]  90.3,64.56 180 top
LED7.51  LED_CROSS1/2  [LED_603]  92.09,64.56 180 top
LED7.52  LED_CROSS1/2  [LED_603]  93.84,64.56 180 top
LED7.53  LED_CROSS1/2  [LED_603]  95.59,64.56 180 top
LED7.54  LED_CROSS1/2  [LED_603]  97.34,64.56 180 top
LED7.55  LED_CROSS1/2  [LED_603]  99.09,64.56 180 top
LED7.56  LED_CROSS1/2  [LED_603]  100.82,64.56 180 top
LED7.57  LED_CROSS1/2  [LED_603]  102.55,64.56 180 top
LED7.58  LED_CROSS1/2  [LED_603]  104.3,64.56 180 top
LED7.59  LED_CROSS1/2  [LED_603]  106.05,64.56 180 top
LED7.60  LED_CROSS1/2  [LED_603]  107.75,64.56 180 top
LED7.61  LED_CROSS1/2  [LED_603]  109.52,64.56 180 top
LED7.62  LED_CROSS1/2  [LED_603]  111.25,64.56 180 top
LED7.63  LED_CROSS1/2  [LED_603]  113.02,64.56 180 top
LED8.0  LED_CROSS1/2  [LED_603]  2.57,61.91 180 top
LED8.1  LED_CROSS1/2  [LED_603]  4.37,61.91 180 top
LED8.2  LED_CROSS1/2  [LED_603]  6.18,61.91 180 top
LED8.3  LED_CROSS1/2  [LED_603]  7.97,61.91 180 top
LED8.4  LED_CROSS1/2  [LED_603]  9.73,61.91 180 top
LED8.5  LED_CROSS1/2  [LED_603]  11.52,61.91 180 top
LED8.6  LED_CROSS1/2  [LED_603]  13.32,61.91 180 top
LED8.7  LED_CROSS1/2  [LED_603]  15.12,61.91 180 top
LED8.8  LED_CROSS1/2  [LED_603]  16.92,61.91 180 top
LED8.9  LED_CROSS1/2  [LED_603]  18.72,61.91 180 top
LED8.10  LED_CROSS1/2  [LED_603]  20.52,61.91 180 top
LED8.11  LED_CROSS1/2  [LED_603]  22.32,61.91 180 top
LED8.12  LED_CROSS1/2  [LED_603]  24.12,61.91 180 top
LED8.13  LED_CROSS1/2  [LED_603]  25.92,61.91 180 top
LED8.14  LED_CROSS1/2  [LED_603]  27.72,61.91 180 top
LED8.15  LED_CROSS1/2  [LED_603]  29.51,61.91 180 top
LED8.16  LED_CROSS1/2  [LED_603]  31.32,61.91 180 top
LED8.17  LED_CROSS1/2  [LED_603]  33.12,61.91 180 top
LED8.18  LED_CROSS1/2  [LED_603]  34.91,61.91 180 top
LED8.19  LED_CROSS1/2  [LED_603]  36.73,61.91 180 top
LED8.20  LED_CROSS1/2  [LED_603]  38.52,61.91 180 top
LED8.21  LED_CROSS1/2  [LED_603]  40.31,61.91 180 top
LED8.22  LED_CROSS1/2  [LED_603]  42.12,61.91 180 top
LED8.23  LED_CROSS1/2  [LED_603]  43.92,61.91 180 top
LED8.24  LED_CROSS1/2  [LED_603]  45.72,61.91 180 top
LED8.25  LED_CROSS1/2  [LED_603]  47.51,61.91 180 top
LED8.26  LED_CROSS1/2  [LED_603]  49.31,61.91 180 top
LED8.27  LED_CROSS1/2  [LED_603]  51.13,61.91 180 top
LED8.28  LED_CROSS1/2  [LED_603]  52.89,61.91 180 top
LED8.29  LED_CROSS1/2  [LED_603]  54.71,61.91 180 top
LED8.30  LED_CROSS1/2  [LED_603]  56.51,61.91 180 top
LED8.31  LED_CROSS1/2  [LED_603]  58.3,61.91 180 top
LED8.33  LED_CROSS1/2  [LED_603]  60.08,61.93 180 top
LED8.34  LED_CROSS1/2  [LED_603]  61.95,61.93 180 top
LED8.35  LED_CROSS1/2  [LED_603]  63.7,61.93 180 top
LED8.36  LED_CROSS1/2  [LED_603]  65.49,61.93 180 top
LED8.37  LED_CROSS1/2  [LED_603]  67.52,61.93 180 top
LED8.38  LED_CROSS1/2  [LED_603]  69.3,61.93 180 top
LED8.39  LED_CROSS1/2  [LED_603]  71.05,61.93 180 top
LED8.40  LED_CROSS1/2  [LED_603]  72.8,61.93 180 top
LED8.41  LED_CROSS1/2  [LED_603]  74.55,61.93 180 top
LED8.42  LED_CROSS1/2  [LED_603]  76.3,61.93 180 top
LED8.43  LED_CROSS1/2  [LED_603]  78.07,61.93 180 top
LED8.44  LED_CROSS1/2  [LED_603]  79.82,61.93 180 top
LED8.45  LED_CROSS1/2  [LED_603]  81.57,61.93 180 top
LED8.46  LED_CROSS1/2  [LED_603]  83.32,61.93 180 top
LED8.47  LED_CROSS1/2  [LED_603]  85.07,61.93 180 top
LED8.48  LED_CROSS1/2  [LED_603]  86.82,61.93 180 top
LED8.49  LED_CROSS1/2  [LED_603]  88.57,61.93 180 top
LED8.50  LED_CROSS1/2  [LED_603]  90.32,61.93 180 top
LED8.51  LED_CROSS1/2  [LED_603]  92.09,61.93 180 top
LED8.52  LED_CROSS1/2  [LED_603]  93.84,61.93 180 top
LED8.53  LED_CROSS1/2  [LED_603]  95.59,61.93 180 top
LED8.54  LED_CROSS1/2  [LED_603]  97.34,61.93 180 top
LED8.55  LED_CROSS1/2  [LED_603]  99.09,61.93 180 top
LED8.56  LED_CROSS1/2  [LED_603]  100.82,61.93 180 top
LED8.57  LED_CROSS1/2  [LED_603]  102.55,61.93 180 top
LED8.58  LED_CROSS1/2  [LED_603]  104.3,61.93 180 top
LED8.59  LED_CROSS1/2  [LED_603]  106.05,61.93 180 top
LED8.60  LED_CROSS1/2  [LED_603]  107.77,61.93 180 top
LED8.61  LED_CROSS1/2  [LED_603]  109.55,61.93 180 top
LED8.62  LED_CROSS1/2  [LED_603]  111.27,61.93 180 top
LED8.63  LED_CROSS1/2  [LED_603]  113.05,61.93 180 top
LED9.0  LED_CROSS1/2  [LED_603]  2.57,59.36 180 top
LED9.1  LED_CROSS1/2  [LED_603]  4.37,59.36 180 top
LED9.2  LED_CROSS1/2  [LED_603]  6.18,59.36 180 top
LED9.3  LED_CROSS1/2  [LED_603]  7.97,59.36 180 top
LED9.4  LED_CROSS1/2  [LED_603]  9.72,59.36 180 top
LED9.5  LED_CROSS1/2  [LED_603]  11.52,59.36 180 top
LED9.6  LED_CROSS1/2  [LED_603]  13.32,59.36 180 top
LED9.7  LED_CROSS1/2  [LED_603]  15.12,59.36 180 top
LED9.8  LED_CROSS1/2  [LED_603]  16.92,59.36 180 top
LED9.9  LED_CROSS1/2  [LED_603]  18.72,59.36 180 top
LED9.10  LED_CROSS1/2  [LED_603]  20.52,59.36 180 top
LED9.11  LED_CROSS1/2  [LED_603]  22.32,59.36 180 top
LED9.12  LED_CROSS1/2  [LED_603]  24.12,59.36 180 top
LED9.13  LED_CROSS1/2  [LED_603]  25.92,59.36 180 top
LED9.14  LED_CROSS1/2  [LED_603]  27.72,59.36 180 top
LED9.15  LED_CROSS1/2  [LED_603]  29.51,59.36 180 top
LED9.16  LED_CROSS1/2  [LED_603]  31.32,59.36 180 top
LED9.17  LED_CROSS1/2  [LED_603]  33.12,59.36 180 top
LED9.18  LED_CROSS1/2  [LED_603]  34.91,59.36 180 top
LED9.19  LED_CROSS1/2  [LED_603]  36.73,59.36 180 top
LED9.20  LED_CROSS1/2  [LED_603]  38.52,59.36 180 top
LED9.21  LED_CROSS1/2  [LED_603]  40.31,59.36 180 top
LED9.22  LED_CROSS1/2  [LED_603]  42.13,59.36 180 top
LED9.23  LED_CROSS1/2  [LED_603]  43.92,59.36 180 top
LED9.24  LED_CROSS1/2  [LED_603]  45.72,59.36 180 top
LED9.25  LED_CROSS1/2  [LED_603]  47.51,59.36 180 top
LED9.26  LED_CROSS1/2  [LED_603]  49.31,59.36 180 top
LED9.27  LED_CROSS1/2  [LED_603]  51.13,59.36 180 top
LED9.28  LED_CROSS1/2  [LED_603]  52.89,59.36 180 top
LED9.29  LED_CROSS1/2  [LED_603]  54.71,59.36 180 top
LED9.30  LED_CROSS1/2  [LED_603]  56.51,59.36 180 top
LED9.31  LED_CROSS1/2  [LED_603]  58.3,59.36 180 top
LED9.33  LED_CROSS1/2  [LED_603]  60.08,59.36 180 top
LED9.34  LED_CROSS1/2  [LED_603]  61.91,59.36 180 top
LED9.35  LED_CROSS1/2  [LED_603]  63.7,59.36 180 top
LED9.36  LED_CROSS1/2  [LED_603]  65.49,59.36 180 top
LED9.37  LED_CROSS1/2  [LED_603]  67.52,59.36 180 top
LED9.38  LED_CROSS1/2  [LED_603]  69.3,59.36 180 top
LED9.39  LED_CROSS1/2  [LED_603]  71.05,59.36 180 top
LED9.40  LED_CROSS1/2  [LED_603]  72.8,59.36 180 top
LED9.41  LED_CROSS1/2  [LED_603]  74.55,59.36 180 top
LED9.42  LED_CROSS1/2  [LED_603]  76.3,59.36 180 top
LED9.43  LED_CROSS1/2  [LED_603]  78.05,59.36 180 top
LED9.44  LED_CROSS1/2  [LED_603]  79.8,59.36 180 top
LED9.45  LED_CROSS1/2  [LED_603]  81.57,59.36 180 top
LED9.46  LED_CROSS1/2  [LED_603]  83.32,59.36 180 top
LED9.47  LED_CROSS1/2  [LED_603]  85.07,59.36 180 top
LED9.48  LED_CROSS1/2  [LED_603]  86.82,59.36 180 top
LED9.49  LED_CROSS1/2  [LED_603]  88.57,59.36 180 top
LED9.50  LED_CROSS1/2  [LED_603]  90.32,59.36 180 top
LED9.51  LED_CROSS1/2  [LED_603]  92.09,59.36 180 top
LED9.52  LED_CROSS1/2  [LED_603]  93.84,59.36 180 top
LED9.53  LED_CROSS1/2  [LED_603]  95.59,59.36 180 top
LED9.54  LED_CROSS1/2  [LED_603]  97.34,59.36 180 top
LED9.55  LED_CROSS1/2  [LED_603]  99.09,59.36 180 top
LED9.56  LED_CROSS1/2  [LED_603]  100.82,59.36 180 top
LED9.57  LED_CROSS1/2  [LED_603]  102.55,59.36 180 top
LED9.58  LED_CROSS1/2  [LED_603]  104.3,59.36 180 top
LED9.59  LED_CROSS1/2  [LED_603]  106.05,59.36 180 top
LED9.60  LED_CROSS1/2  [LED_603]  107.8,59.36 180 top
LED9.61  LED_CROSS1/2  [LED_603]  109.55,59.36 180 top
LED9.62  LED_CROSS1/2  [LED_603]  111.3,59.36 180 top
LED9.63  LED_CROSS1/2  [LED_603]  113.05,59.36 180 top
LED10.0  [LED_603]  2.57,56.63 180 top
LED10.1  [LED_603]  4.37,56.63 180 top
LED10.2  [LED_603]  6.18,56.63 180 top
LED10.3  [LED_603]  7.97,56.63 180 top
LED10.4  [LED_603]  9.72,56.63 180 top
LED10.5  [LED_603]  11.52,56.63 180 top
LED10.6  [LED_603]  13.32,56.63 180 top
LED10.7  [LED_603]  15.12,56.63 180 top
LED10.8  [LED_603]  16.92,56.63 180 top
LED10.9  [LED_603]  18.72,56.63 180 top
LED10.10  [LED_603]  20.52,56.63 180 top
LED10.11  [LED_603]  22.32,56.63 180 top
LED10.12  [LED_603]  24.12,56.63 180 top
LED10.13  [LED_603]  25.92,56.63 180 top
LED10.14  [LED_603]  27.72,56.63 180 top
LED10.15  [LED_603]  29.51,56.63 180 top
LED10.16  [LED_603]  31.32,56.63 180 top
LED10.17  [LED_603]  33.12,56.63 180 top
LED10.18  [LED_603]  34.91,56.63 180 top
LED10.19  [LED_603]  36.73,56.63 180 top
LED10.20  [LED_603]  38.52,56.63 180 top
LED10.21  [LED_603]  40.31,56.63 180 top
LED10.22  [LED_603]  42.13,56.63 180 top
LED10.23  [LED_603]  43.92,56.63 180 top
LED10.24  [LED_603]  45.72,56.63 180 top
LED10.25  [LED_603]  47.51,56.63 180 top
LED10.26  [LED_603]  49.31,56.63 180 top
LED10.27  [LED_603]  51.13,56.63 180 top
LED10.28  [LED_603]  52.89,56.63 180 top
LED10.29  [LED_603]  54.71,56.63 180 top
LED10.30  [LED_603]  56.51,56.63 180 top
LED10.31  [LED_603]  58.3,56.63 180 top
LED10.33  [LED_603]  60.09,56.63 180 top
LED10.34  [LED_603]  61.91,56.63 180 top
LED10.35  [LED_603]  63.7,56.63 180 top
LED10.36  [LED_603]  65.49,56.63 180 top
LED10.37  [LED_603]  67.52,56.63 180 top
LED10.38  [LED_603]  69.3,56.63 180 top
LED10.39  [LED_603]  71.05,56.63 180 top
LED10.40  [LED_603]  72.8,56.63 180 top
LED10.41  [LED_603]  74.55,56.63 180 top
LED10.42  [LED_603]  76.3,56.63 180 top
LED10.43  [LED_603]  78.05,56.63 180 top
LED10.44  [LED_603]  79.8,56.63 180 top
LED10.45  [LED_603]  81.57,56.63 180 top
LED10.46  [LED_603]  83.32,56.63 180 top
LED10.47  [LED_603]  85.07,56.63 180 top
LED10.48  [LED_603]  86.82,56.63 180 top
LED10.49  [LED_603]  88.57,56.63 180 top
LED10.50  [LED_603]  90.32,56.63 180 top
LED10.51  [LED_603]  92.09,56.63 180 top
LED10.52  [LED_603]  93.84,56.63 180 top
LED10.53  [LED_603]  95.59,56.63 180 top
LED10.54  [LED_603]  97.34,56.63 180 top
LED10.55  [LED_603]  99.09,56.63 180 top
LED10.56  [LED_603]  100.82,56.63 180 top
LED10.57  [LED_603]  102.55,56.63 180 top
LED10.58  [LED_603]  104.3,56.63 180 top
LED10.59  [LED_603]  106.05,56.63 180 top
LED10.60  [LED_603]  107.8,56.63 180 top
LED10.61  [LED_603]  109.55,56.63 180 top
LED10.62  [LED_603]  111.3,56.63 180 top
LED10.63  [LED_603]  113.05,56.63 180 top
LED11.0  LED_CROSS1/2  [LED_603]  2.57,53.92 180 top
LED11.1  LED_CROSS1/2  [LED_603]  4.37,53.92 180 top
LED11.2  LED_CROSS1/2  [LED_603]  6.18,53.92 180 top
LED11.3  LED_CROSS1/2  [LED_603]  7.98,53.92 180 top
LED11.4  LED_CROSS1/2  [LED_603]  9.72,53.92 180 top
LED11.5  LED_CROSS1/2  [LED_603]  11.52,53.92 180 top
LED11.6  LED_CROSS1/2  [LED_603]  13.33,53.92 180 top
LED11.7  LED_CROSS1/2  [LED_603]  15.12,53.92 180 top
LED11.8  LED_CROSS1/2  [LED_603]  16.92,53.92 180 top
LED11.9  LED_CROSS1/2  [LED_603]  18.72,53.92 180 top
LED11.10  LED_CROSS1/2  [LED_603]  20.52,53.92 180 top
LED11.11  LED_CROSS1/2  [LED_603]  22.32,53.92 180 top
LED11.12  LED_CROSS1/2  [LED_603]  24.12,53.92 180 top
LED11.13  LED_CROSS1/2  [LED_603]  25.92,53.92 180 top
LED11.14  LED_CROSS1/2  [LED_603]  27.72,53.92 180 top
LED11.15  LED_CROSS1/2  [LED_603]  29.52,53.92 180 top
LED11.16  LED_CROSS1/2  [LED_603]  31.32,53.92 180 top
LED11.17  LED_CROSS1/2  [LED_603]  33.11,53.92 180 top
LED11.18  LED_CROSS1/2  [LED_603]  34.92,53.92 180 top
LED11.19  LED_CROSS1/2  [LED_603]  36.72,53.92 180 top
LED11.20  LED_CROSS1/2  [LED_603]  38.51,53.92 180 top
LED11.21  LED_CROSS1/2  [LED_603]  40.33,53.92 180 top
LED11.22  LED_CROSS1/2  [LED_603]  42.12,53.92 180 top
LED11.23  LED_CROSS1/2  [LED_603]  43.91,53.92 180 top
LED11.24  LED_CROSS1/2  [LED_603]  45.71,53.92 180 top
LED11.25  LED_CROSS1/2  [LED_603]  47.5,53.92 180 top
LED11.26  LED_CROSS1/2  [LED_603]  49.3,53.92 180 top
LED11.27  LED_CROSS1/2  [LED_603]  51.12,53.92 180 top
LED11.28  LED_CROSS1/2  [LED_603]  52.91,53.92 180 top
LED11.29  LED_CROSS1/2  [LED_603]  54.71,53.92 180 top
LED11.30  LED_CROSS1/2  [LED_603]  56.5,53.92 180 top
LED11.31  LED_CROSS1/2  [LED_603]  58.33,53.92 180 top
LED11.33  LED_CROSS1/2  [LED_603]  60.09,53.92 180 top
LED11.34  LED_CROSS1/2  [LED_603]  61.91,53.92 180 top
LED11.35  LED_CROSS1/2  [LED_603]  63.7,53.92 180 top
LED11.36  LED_CROSS1/2  [LED_603]  65.48,53.92 180 top
LED11.37  LED_CROSS1/2  [LED_603]  67.28,53.92 180 top
LED11.38  LED_CROSS1/2  [LED_603]  69.08,53.92 180 top
LED11.39  LED_CROSS1/2  [LED_603]  70.88,53.92 180 top
LED11.40  LED_CROSS1/2  [LED_603]  72.63,53.92 180 top
LED11.41  LED_CROSS1/2  [LED_603]  74.36,53.92 180 top
LED11.42  LED_CROSS1/2  [LED_603]  76.08,53.92 180 top
LED11.43  LED_CROSS1/2  [LED_603]  77.86,53.92 180 top
LED11.44  LED_CROSS1/2  [LED_603]  79.61,53.92 180 top
LED11.45  LED_CROSS1/2  [LED_603]  81.33,53.92 180 top
LED11.46  LED_CROSS1/2  [LED_603]  83.16,53.92 180 top
LED11.47  LED_CROSS1/2  [LED_603]  84.91,53.92 180 top
LED11.48  LED_CROSS1/2  [LED_603]  86.63,53.92 180 top
LED11.49  LED_CROSS1/2  [LED_603]  88.41,53.92 180 top
LED11.50  LED_CROSS1/2  [LED_603]  90.13,53.92 180 top
LED11.51  LED_CROSS1/2  [LED_603]  91.91,53.92 180 top
LED11.52  LED_CROSS1/2  [LED_603]  93.83,53.92 180 top
LED11.53  LED_CROSS1/2  [LED_603]  95.61,53.92 180 top
LED11.54  LED_CROSS1/2  [LED_603]  97.33,53.92 180 top
LED11.55  LED_CROSS1/2  [LED_603]  99.11,53.92 180 top
LED11.56  LED_CROSS1/2  [LED_603]  100.8,53.92 180 top
LED11.57  LED_CROSS1/2  [LED_603]  102.55,53.92 180 top
LED11.58  LED_CROSS1/2  [LED_603]  104.25,53.92 180 top
LED11.59  LED_CROSS1/2  [LED_603]  106.05,53.92 180 top
LED11.60  LED_CROSS1/2  [LED_603]  107.8,53.92 180 top
LED11.61  LED_CROSS1/2  [LED_603]  109.53,53.92 180 top
LED11.62  LED_CROSS1/2  [LED_603]  111.28,53.92 180 top
LED11.63  LED_CROSS1/2  [LED_603]  113.05,53.92 180 top
LED11.64  LED_CROSS1/2  [LED_603]  2.57,25.07 180 top
LED11.65  LED_CROSS1/2  [LED_603]  4.37,25.07 180 top
LED11.66  LED_CROSS1/2  [LED_603]  6.18,25.07 180 top
LED11.67  LED_CROSS1/2  [LED_603]  7.98,25.07 180 top
LED11.68  LED_CROSS1/2  [LED_603]  9.72,25.07 180 top
LED11.69  LED_CROSS1/2  [LED_603]  11.52,25.07 180 top
LED11.70  LED_CROSS1/2  [LED_603]  13.33,25.07 180 top
LED11.71  LED_CROSS1/2  [LED_603]  15.11,25.07 180 top
LED11.72  LED_CROSS1/2  [LED_603]  16.92,25.07 180 top
LED11.73  LED_CROSS1/2  [LED_603]  18.72,25.07 180 top
LED11.74  LED_CROSS1/2  [LED_603]  20.52,25.07 180 top
LED11.75  LED_CROSS1/2  [LED_603]  22.32,25.07 180 top
LED11.76  LED_CROSS1/2  [LED_603]  24.12,25.07 180 top
LED11.77  LED_CROSS1/2  [LED_603]  25.92,25.07 180 top
LED11.78  LED_CROSS1/2  [LED_603]  27.72,25.07 180 top
LED11.79  LED_CROSS1/2  [LED_603]  29.52,25.07 180 top
LED11.80  LED_CROSS1/2  [LED_603]  31.31,25.07 180 top
LED11.81  LED_CROSS1/2  [LED_603]  33.11,25.07 180 top
LED11.82  LED_CROSS1/2  [LED_603]  34.92,25.07 180 top
LED11.83  LED_CROSS1/2  [LED_603]  36.72,25.07 180 top
LED11.84  LED_CROSS1/2  [LED_603]  38.53,25.07 180 top
LED11.85  LED_CROSS1/2  [LED_603]  40.33,25.07 180 top
LED11.86  LED_CROSS1/2  [LED_603]  42.12,25.07 180 top
LED11.87  LED_CROSS1/2  [LED_603]  43.92,25.07 180 top
LED11.88  LED_CROSS1/2  [LED_603]  45.71,25.07 180 top
LED11.89  LED_CROSS1/2  [LED_603]  47.5,25.07 180 top
LED11.90  LED_CROSS1/2  [LED_603]  49.3,25.07 180 top
LED11.91  LED_CROSS1/2  [LED_603]  51.12,25.05 180 top
LED11.92  LED_CROSS1/2  [LED_603]  52.91,25.07 180 top
LED11.93  LED_CROSS1/2  [LED_603]  54.71,25.07 180 top
LED11.94  LED_CROSS1/2  [LED_603]  56.51,25.07 180 top
LED11.95  LED_CROSS1/2  [LED_603]  58.3,25.07 180 top
LED11.96  LED_CROSS1/2  [LED_603]  60.11,22.46 180 top
LED11.97  LED_CROSS1/2  [LED_603]  60.1,25.07 180 top
LED11.98  LED_CROSS1/2  [LED_603]  61.93,25.07 180 top
LED11.99  LED_CROSS1/2  [LED_603]  63.68,25.07 180 top
LED11.100  LED_CROSS1/2  [LED_603]  65.5,25.07 180 top
LED11.101  LED_CROSS1/2  [LED_603]  67.38,25.07 180 top
LED11.102  LED_CROSS1/2  [LED_603]  69.14,25.07 180 top
LED11.103  LED_CROSS1/2  [LED_603]  70.88,25.07 180 top
LED11.104  LED_CROSS1/2  [LED_603]  72.68,25.07 180 top
LED11.105  LED_CROSS1/2  [LED_603]  74.41,25.07 180 top
LED11.106  LED_CROSS1/2  [LED_603]  76.18,25.07 180 top
LED11.107  LED_CROSS1/2  [LED_603]  77.91,25.07 180 top
LED11.108  LED_CROSS1/2  [LED_603]  79.66,25.07 180 top
LED11.109  LED_CROSS1/2  [LED_603]  81.48,25.07 180 top
LED11.110  LED_CROSS1/2  [LED_603]  83.16,25.07 180 top
LED11.111  LED_CROSS1/2  [LED_603]  84.91,25.07 180 top
LED11.112  LED_CROSS1/2  [LED_603]  86.68,25.07 180 top
LED11.113  LED_CROSS1/2  [LED_603]  88.44,25.07 180 top
LED11.114  LED_CROSS1/2  [LED_603]  90.13,25.07 180 top
LED11.115  LED_CROSS1/2  [LED_603]  91.95,25.07 180 top
LED11.116  LED_CROSS1/2  [LED_603]  93.73,25.07 180 top
LED11.117  LED_CROSS1/2  [LED_603]  95.45,25.07 180 top
LED11.118  LED_CROSS1/2  [LED_603]  97.18,25.07 180 top
LED11.119  LED_CROSS1/2  [LED_603]  98.91,25.07 180 top
LED11.120  LED_CROSS1/2  [LED_603]  100.66,25.07 180 top
LED11.121  LED_CROSS1/2  [LED_603]  102.41,25.07 180 top
LED11.122  LED_CROSS1/2  [LED_603]  104.16,25.07 180 top
LED11.123  LED_CROSS1/2  [LED_603]  105.91,25.07 180 top
LED11.124  LED_CROSS1/2  [LED_603]  107.61,25.07 180 top
LED11.125  LED_CROSS1/2  [LED_603]  109.38,25.07 180 top
LED11.126  LED_CROSS1/2  [LED_603]  111.08,25.07 180 top
LED11.127  LED_CROSS1/2  [LED_603]  112.86,25.07 180 top
LED12.0  LED_CROSS1/2  [LED_603]  2.57,51.32 180 top
LED12.1  LED_CROSS1/2  [LED_603]  4.37,51.32 180 top
LED12.2  LED_CROSS1/2  [LED_603]  6.18,51.32 180 top
LED12.3  LED_CROSS1/2  [LED_603]  7.97,51.32 180 top
LED12.4  LED_CROSS1/2  [LED_603]  9.72,51.32 180 top
LED12.5  LED_CROSS1/2  [LED_603]  11.52,51.31 180 top
LED12.6  LED_CROSS1/2  [LED_603]  13.32,51.31 180 top
LED12.7  LED_CROSS1/2  [LED_603]  15.12,51.31 180 top
LED12.8  LED_CROSS1/2  [LED_603]  16.92,51.31 180 top
LED12.9  LED_CROSS1/2  [LED_603]  18.72,51.31 180 top
LED12.10  LED_CROSS1/2  [LED_603]  20.52,51.31 180 top
LED12.11  LED_CROSS1/2  [LED_603]  22.32,51.31 180 top
LED12.12  LED_CROSS1/2  [LED_603]  24.12,51.31 180 top
LED12.13  LED_CROSS1/2  [LED_603]  25.91,51.31 180 top
LED12.14  LED_CROSS1/2  [LED_603]  27.72,51.31 180 top
LED12.15  LED_CROSS1/2  [LED_603]  29.52,51.31 180 top
LED12.16  LED_CROSS1/2  [LED_603]  31.32,51.32 180 top
LED12.17  LED_CROSS1/2  [LED_603]  33.11,51.32 180 top
LED12.18  LED_CROSS1/2  [LED_603]  34.93,51.32 180 top
LED12.19  LED_CROSS1/2  [LED_603]  36.72,51.32 180 top
LED12.20  LED_CROSS1/2  [LED_603]  38.53,51.32 180 top
LED12.21  LED_CROSS1/2  [LED_603]  40.33,51.32 180 top
LED12.22  LED_CROSS1/2  [LED_603]  42.12,51.32 180 top
LED12.23  LED_CROSS1/2  [LED_603]  43.91,51.32 180 top
LED12.24  LED_CROSS1/2  [LED_603]  45.71,51.32 180 top
LED12.25  LED_CROSS1/2  [LED_603]  47.5,51.32 180 top
LED12.26  LED_CROSS1/2  [LED_603]  49.3,51.32 180 top
LED12.27  LED_CROSS1/2  [LED_603]  51.12,51.32 180 top
LED12.28  LED_CROSS1/2  [LED_603]  52.91,51.32 180 top
LED12.29  LED_CROSS1/2  [LED_603]  54.7,51.32 180 top
LED12.30  LED_CROSS1/2  [LED_603]  56.5,51.32 180 top
LED12.31  LED_CROSS1/2  [LED_603]  58.3,51.32 180 top
LED12.33  LED_CROSS1/2  [LED_603]  60.09,51.32 180 top
LED12.34  LED_CROSS1/2  [LED_603]  61.91,51.32 180 top
LED12.35  LED_CROSS1/2  [LED_603]  63.7,51.32 180 top
LED12.36  LED_CROSS1/2  [LED_603]  65.48,51.32 180 top
LED12.37  LED_CROSS1/2  [LED_603]  67.3,51.32 180 top
LED12.38  LED_CROSS1/2  [LED_603]  69.08,51.32 180 top
LED12.39  LED_CROSS1/2  [LED_603]  70.88,51.32 180 top
LED12.40  LED_CROSS1/2  [LED_603]  72.63,51.32 180 top
LED12.41  LED_CROSS1/2  [LED_603]  74.36,51.32 180 top
LED12.42  LED_CROSS1/2  [LED_603]  76.08,51.32 180 top
LED12.43  LED_CROSS1/2  [LED_603]  77.86,51.32 180 top
LED12.44  LED_CROSS1/2  [LED_603]  79.61,51.32 180 top
LED12.45  LED_CROSS1/2  [LED_603]  81.33,51.32 180 top
LED12.46  LED_CROSS1/2  [LED_603]  83.16,51.32 180 top
LED12.47  LED_CROSS1/2  [LED_603]  84.91,51.32 180 top
LED12.48  LED_CROSS1/2  [LED_603]  86.63,51.32 180 top
LED12.49  LED_CROSS1/2  [LED_603]  88.41,51.32 180 top
LED12.50  LED_CROSS1/2  [LED_603]  90.16,51.32 180 top
LED12.51  LED_CROSS1/2  [LED_603]  91.93,51.32 180 top
LED12.52  LED_CROSS1/2  [LED_603]  93.83,51.32 180 top
LED12.53  LED_CROSS1/2  [LED_603]  95.61,51.32 180 top
LED12.54  LED_CROSS1/2  [LED_603]  97.33,51.32 180 top
LED12.55  LED_CROSS1/2  [LED_603]  99.11,51.32 180 top
LED12.56  LED_CROSS1/2  [LED_603]  100.86,51.32 180 top
LED12.57  LED_CROSS1/2  [LED_603]  102.58,51.32 180 top
LED12.58  LED_CROSS1/2  [LED_603]  104.16,51.32 180 top
LED12.59  LED_CROSS1/2  [LED_603]  105.91,51.32 180 top
LED12.60  LED_CROSS1/2  [LED_603]  107.61,51.32 180 top
LED12.61  LED_CROSS1/2  [LED_603]  109.33,51.29 180 top
LED12.62  LED_CROSS1/2  [LED_603]  111.08,51.29 180 top
LED12.63  LED_CROSS1/2  [LED_603]  112.86,51.29 180 top
LED12.64  LED_CROSS1/2  [LED_603]  2.57,22.46 180 top
LED12.65  LED_CROSS1/2  [LED_603]  4.37,22.46 180 top
LED12.66  LED_CROSS1/2  [LED_603]  6.17,22.46 180 top
LED12.67  LED_CROSS1/2  [LED_603]  7.97,22.46 180 top
LED12.68  LED_CROSS1/2  [LED_603]  9.72,22.45 180 top
LED12.69  LED_CROSS1/2  [LED_603]  11.52,22.46 180 top
LED12.70  LED_CROSS1/2  [LED_603]  13.32,22.46 180 top
LED12.71  LED_CROSS1/2  [LED_603]  15.12,22.46 180 top
LED12.72  LED_CROSS1/2  [LED_603]  16.93,22.45 180 top
LED12.73  LED_CROSS1/2  [LED_603]  18.72,22.45 180 top
LED12.74  LED_CROSS1/2  [LED_603]  20.52,22.46 180 top
LED12.75  LED_CROSS1/2  [LED_603]  22.32,22.46 180 top
LED12.76  LED_CROSS1/2  [LED_603]  24.12,22.46 180 top
LED12.77  LED_CROSS1/2  [LED_603]  25.91,22.46 180 top
LED12.78  LED_CROSS1/2  [LED_603]  27.71,22.45 180 top
LED12.79  LED_CROSS1/2  [LED_603]  29.52,22.46 180 top
LED12.80  LED_CROSS1/2  [LED_603]  31.32,22.47 180 top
